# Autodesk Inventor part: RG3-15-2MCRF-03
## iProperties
Created: 2008-09
Part Number: RG3-15-2MCRF-03
Material: 1.0037.07 St 37k
Document SubType Name: Modeling
Designer: TMT
Density: 7.85 g/cm^3
Mass: 8.85038 g
Surface Area: 9.86557 cm^2
Volume: 1.12744 cm^3
Author: TMT
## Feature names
1. Sweeping1
2. Extrusion1
3. Rundung1 [Fillet]
